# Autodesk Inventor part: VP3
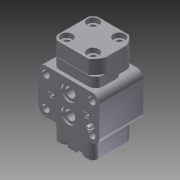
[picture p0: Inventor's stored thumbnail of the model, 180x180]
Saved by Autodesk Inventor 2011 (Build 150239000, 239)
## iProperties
Created: 2012-01
Part Number: VP3
Document SubType Name: Modeling
Designer: khramov
Density: 1 g/cm^3
Author: khramov
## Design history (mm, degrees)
derived "VP3_P2_MU_12.iam"
node "Твердое тело1"
node "0111380_.ipt:1"
node "0111232_.ipt:1"
sketch "0530077_UNI_5931___M10x20.ipt:1"
sketch "0530077_UNI_5931___M10x20.ipt:2"
sketch "0530077_UNI_5931___M10x20.ipt:3"
sketch "0530077_UNI_5931___M10x20.ipt:4"
node "0111235_.ipt:1"
sketch "0530077_UNI_5931___M10x20.ipt:5"
sketch "0530077_UNI_5931___M10x20.ipt:6"
sketch "0530077_UNI_5931___M10x20.ipt:7"
sketch "0530077_UNI_5931___M10x20.ipt:8"
sketch "3001050000_.ipt:1"
sketch "0550326_DIN_1481_6x16.ipt:1"
